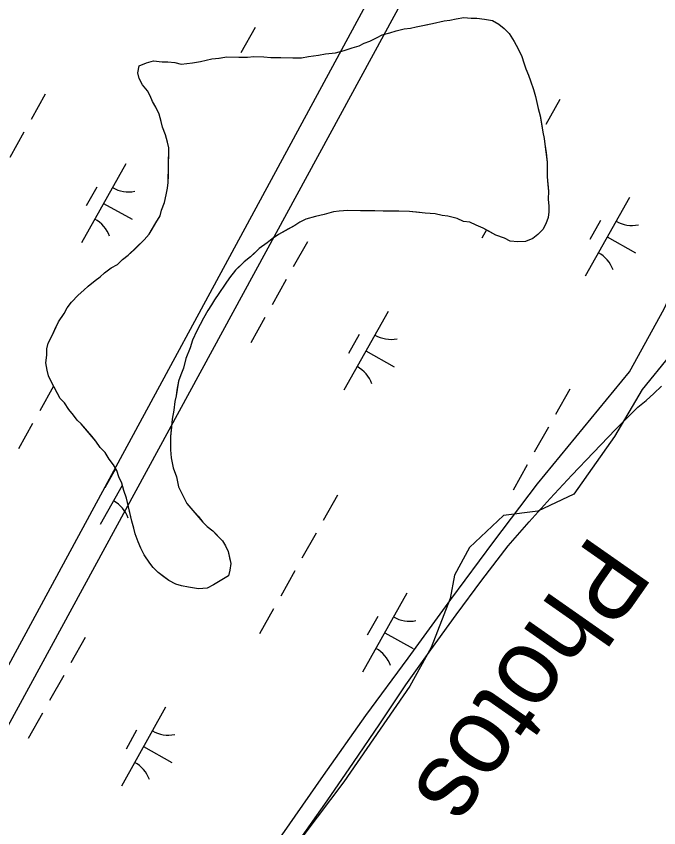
# Model space of a CAD drawing. Extents: x 3913936 to 3933962, y 195330 to 217741.
# Drawn here: x 3926148.2 to 3926503.4, y 209335.7 to 209784.3 of the extents above; entities that cross this region are included whole.
import ezdxf

# ---------------------------------------------------------------- set-up
doc = ezdxf.new("R2010")
doc.units = 0
for name, color, linetype in [('V-RIVR-EDGE', 7, 'Continuous'), ('V-RIVR-IDEN', 7, 'Continuous'), ('V-RRAP-FSHR', 7, 'Continuous'), ('V-TOPO-SHOR', 7, 'Continuous'), ('V-UTIL-LINE', 7, 'Continuous'), ('V-WETL-SWMP', 7, 'Continuous')]:
    doc.layers.add(name, color=color, linetype=linetype)

msp = doc.modelspace()

# ---------------------------------------------------------------- linework, layer by layer
at = {"layer": 'V-RIVR-EDGE'}
msp.add_lwpolyline([(3926892.67, 210182.59), (3926854.95, 210131.91), (3926814.88, 210070.61), (3926787.77, 210030.54), (3926744.16, 209975.14), (3926680.51, 209878.48), (3926634.54, 209811.3), (3926563.81, 209712.28), (3926562.63, 209685.17), (3926537.88, 209634.49), (3926509.59, 209596.77), (3926494.27, 209577.91), (3926478.94, 209551.98), (3926456.55, 209520.15), (3926436.51, 209510.72), (3926417.65, 209508.37), (3926398.79, 209490.69), (3926390.54, 209475.36), (3926388.18, 209462.4), (3926377.58, 209435.29), (3926365.79, 209414.07), (3926329.25, 209361.03), (3926299.78, 209322.13)], dxfattribs=at)
at = {"layer": 'V-RRAP-FSHR'}
msp.add_lwpolyline([(3926144.53, 209096.38), (3926165.14, 209130.13), (3926186.84, 209163.74), (3926208.53, 209197.34), (3926230.22, 209230.95), (3926251.92, 209264.55), (3926273.61, 209298.16), (3926295.31, 209331.77), (3926318.1, 209364.69), (3926341.47, 209397.75), (3926364.94, 209429.46), (3926388.41, 209461.85), (3926412.27, 209493.96), (3926436.47, 209525.8), (3926461.82, 209556.74), (3926487.16, 209587.69), (3926506.32, 209622.52), (3926523.2, 209658.79), (3926542.21, 209693.94), (3926562.2, 209728.58), (3926583.45, 209762.45)], dxfattribs=at)
at = {"layer": 'V-TOPO-SHOR'}
for points in [[(3926250.08, 209759.22), (3926253.23, 209759.97), (3926256.38, 209760.71), (3926260.32, 209761.05), (3926264.65, 209761.78), (3926271.32, 209761.69), (3926276.03, 209761.63), (3926279.57, 209761.98), (3926285.07, 209761.9), (3926288.99, 209761.46), (3926294.49, 209761.38), (3926301.17, 209761.3), (3926305.88, 209761.23), (3926309.82, 209761.97), (3926315.33, 209762.68), (3926319.26, 209763.41), (3926324.77, 209764.12), (3926329.5, 209765.24), (3926333.84, 209766.76), (3926337.78, 209767.88), (3926340.55, 209769.42), (3926343.71, 209770.55), (3926347.66, 209772.46), (3926350.43, 209774), (3926354.77, 209775.12), (3926358.32, 209776.25), (3926362.65, 209777.37), (3926366.19, 209777.72), (3926369.35, 209778.46), (3926374.86, 209779.57), (3926378.4, 209780.31), (3926384.71, 209781.79), (3926387.85, 209782.15), (3926391.4, 209782.88), (3926395.73, 209783.61), (3926399.65, 209783.17), (3926402.79, 209783.12), (3926407.11, 209782.68), (3926411.42, 209781.83), (3926414.93, 209779.82), (3926418.04, 209777.43), (3926420.75, 209774.64), (3926423.44, 209770.28), (3926425.75, 209766.33), (3926427.65, 209761.98), (3926428.78, 209758.43), (3926429.92, 209755.27), (3926431.44, 209751.72), (3926432.58, 209748.56), (3926434.09, 209743.83), (3926435.21, 209739.88), (3926436.7, 209733.19), (3926437.82, 209729.24), (3926438.55, 209724.91), (3926439.27, 209720.19), (3926440.01, 209716.65), (3926440.37, 209713.5), (3926441.09, 209708.78), (3926441.81, 209703.66), (3926441.76, 209700.12), (3926441.7, 209695.42), (3926442.03, 209691.09), (3926442.38, 209687.55), (3926442.32, 209683.23), (3926442.66, 209679.3), (3926442.62, 209676.16), (3926442.19, 209673.02), (3926440.96, 209669.5), (3926439.35, 209666.38), (3926436.56, 209663.67), (3926433.78, 209661.35), (3926429.83, 209659.83), (3926425.51, 209659.49), (3926421.19, 209659.94), (3926418.07, 209661.55), (3926413.38, 209663.19), (3926409.1, 209665.6), (3926406.37, 209667.21), (3926402.46, 209668.83), (3926398.95, 209670.45), (3926395.42, 209670.89), (3926391.9, 209672.51), (3926386.81, 209673.75), (3926383.68, 209674.18), (3926379.76, 209675.02), (3926374.27, 209675.49), (3926369.56, 209675.94), (3926365.64, 209676.39), (3926359.75, 209676.47), (3926355.04, 209676.53), (3926351.11, 209676.58), (3926346.4, 209676.64), (3926341.68, 209676.7), (3926338.54, 209676.75), (3926331.47, 209676.84), (3926326.75, 209676.51), (3926323.61, 209676.16), (3926318.48, 209674.65), (3926313.75, 209673.54), (3926308.23, 209672.04), (3926305.07, 209670.51)], [(3926257.25, 209470.04), (3926253.69, 209468.13), (3926248.97, 209467.79), (3926243.48, 209468.65), (3926239.57, 209469.49), (3926236.44, 209470.32), (3926232.54, 209472.33), (3926229.81, 209474.33), (3926226.7, 209476.73), (3926223.99, 209479.52), (3926222.06, 209481.9), (3926218.98, 209486.65), (3926217.06, 209490.21), (3926215.54, 209493.77), (3926214.02, 209498.11), (3926213.28, 209501.26), (3926212.15, 209505.2), (3926211.41, 209508.36), (3926210.29, 209513.08), (3926209.18, 209517.81), (3926207.66, 209522.15), (3926206.54, 209526.1), (3926205.01, 209529.65), (3926203.88, 209533.2), (3926201.96, 209536.37), (3926199.65, 209539.54), (3926197.34, 209543.11), (3926194.62, 209545.89), (3926192.31, 209549.46), (3926189.99, 209552.24), (3926186.51, 209556.21), (3926184.19, 209558.99), (3926181.86, 209560.99), (3926179.93, 209563.76), (3926177.23, 209566.94), (3926174.92, 209570.5), (3926172.59, 209572.89), (3926171.06, 209575.66), (3926169.14, 209579.22), (3926167.61, 209582.38), (3926166.08, 209585.55), (3926165.34, 209588.7), (3926164.6, 209592.64), (3926165.06, 209596.95), (3926165.1, 209600.48), (3926165.93, 209603.62), (3926167.95, 209607.52), (3926169.56, 209611.03), (3926171.58, 209615.33), (3926174.79, 209619.99), (3926176.4, 209623.12), (3926178.8, 209626.23), (3926182.38, 209630.11), (3926185.56, 209632.82), (3926187.95, 209635.14), (3926191.92, 209638.23), (3926194.69, 209640.16), (3926197.08, 209642.48), (3926200.65, 209645.19), (3926204.21, 209647.1), (3926207, 209649.81), (3926210.17, 209652.13), (3926213.35, 209655.23), (3926215.74, 209657.55), (3926218.92, 209660.65), (3926221.71, 209663.76), (3926223.32, 209666.49), (3926225.33, 209669.99), (3926227.74, 209673.89), (3926228.57, 209677.02), (3926230.19, 209681.32), (3926231.04, 209685.63), (3926231.87, 209689.16), (3926232.3, 209692.29), (3926232.35, 209696.22), (3926232.4, 209699.76), (3926232.45, 209703.29), (3926232.5, 209707.22), (3926232.56, 209711.54), (3926231.81, 209714.69), (3926230.69, 209718.63), (3926229.17, 209722.97), (3926228.43, 209726.12), (3926227.3, 209730.07), (3926225.39, 209734.02), (3926223.47, 209737.19), (3926222.33, 209740.34), (3926220.8, 209743.11), (3926218.09, 209746.29), (3926216.18, 209749.85), (3926215.43, 209753.01), (3926216.27, 209756.92), (3926220.22, 209758.44), (3926224.16, 209759.56), (3926228.87, 209759.11), (3926232.01, 209759.07), (3926235.93, 209758.62), (3926239.46, 209757.79), (3926242.6, 209758.14), (3926245.75, 209758.49), (3926250.08, 209759.22)], [(3926305.07, 209670.51), (3926302.3, 209668.58), (3926298.74, 209666.67), (3926293.2, 209663.6), (3926289.63, 209661.29), (3926286.85, 209658.97), (3926282.49, 209655.88), (3926280.1, 209653.56), (3926277.72, 209651.24), (3926274.15, 209648.53), (3926271.76, 209646.21), (3926269.37, 209643.88), (3926266.17, 209639.61), (3926263.77, 209636.1), (3926260.17, 209631.04), (3926257.76, 209627.54), (3926256.16, 209624.81), (3926254.15, 209621.7), (3926251.74, 209617.41), (3926248.11, 209610.38), (3926245.69, 209605.31), (3926244.45, 209601.01), (3926242.02, 209595.15), (3926240.77, 209589.66), (3926239.15, 209586.15), (3926237.92, 209582.63), (3926237.07, 209577.54), (3926236.64, 209574.4), (3926235.81, 209571.27), (3926235.35, 209566.56), (3926234.5, 209561.47), (3926234.05, 209557.15), (3926233.59, 209552.05), (3926233.54, 209548.13), (3926233.49, 209544.59), (3926233.83, 209540.27), (3926234.93, 209534.75), (3926236.83, 209529.62), (3926237.93, 209524.11), (3926240.61, 209518.57), (3926242.53, 209515.01), (3926245.62, 209511.44), (3926248.72, 209507.86), (3926251.42, 209504.68), (3926253.75, 209502.3), (3926256.86, 209499.9), (3926259.19, 209497.51), (3926262.29, 209494.33), (3926263.82, 209491.56), (3926265.35, 209488.4), (3926266.09, 209484.85), (3926266.83, 209481.7), (3926266.39, 209478.17), (3926265.56, 209475.04), (3926257.25, 209470.04)]]:
    msp.add_lwpolyline(points, dxfattribs=at)
at = {"layer": 'V-UTIL-LINE'}
for points in [[(3928315.82, 212388.13), (3926944.7, 210748.94), (3926592.74, 210251.47), (3926408.93, 209914.99), (3925628.64, 208474.44), (3925139.98, 207727.42), (3924555.96, 206253.65), (3924055.82, 204771.45), (3923484.9, 203858.52), (3922256.01, 202262.65), (3921816.4, 201905.57), (3920704.84, 200345.08), (3920462.44, 200062.72)], [(3928328.32, 212380.93), (3926784.14, 210502.92), (3926424.72, 209908.68), (3925640.45, 208467.64), (3924952.2, 207329.25), (3923971.74, 204752.16), (3923252.9, 203563.68), (3921560.17, 201558.84), (3920397.87, 200112.86)]]:
    msp.add_lwpolyline(points, dxfattribs=at)
at = {"layer": 'V-WETL-SWMP'}
for p, q in [((3926378.4, 209780.31), (3926384.71, 209781.79)), ((3926384.71, 209781.79), (3926387.85, 209782.15)), ((3926387.85, 209782.15), (3926391.4, 209782.88)), ((3926391.4, 209782.88), (3926395.73, 209783.61)), ((3926395.73, 209783.61), (3926399.65, 209783.17)), ((3926399.65, 209783.17), (3926402.79, 209783.12)), ((3926402.79, 209783.12), (3926407.11, 209782.68)), ((3926407.11, 209782.68), (3926411.42, 209781.83)), ((3926411.42, 209781.83), (3926414.93, 209779.82)), ((3926280.24, 209777.95), (3926272.4, 209764.01)), ((3926358.32, 209776.25), (3926362.65, 209777.37)), ((3926362.65, 209777.37), (3926366.19, 209777.72)), ((3926366.19, 209777.72), (3926369.35, 209778.46)), ((3926369.35, 209778.46), (3926378.4, 209780.31)), ((3926414.93, 209779.82), (3926418.04, 209777.43)), ((3926418.04, 209777.43), (3926420.75, 209774.64)), ((3926343.71, 209770.55), (3926347.66, 209772.46)), ((3926347.66, 209772.46), (3926350.43, 209774)), ((3926350.43, 209774), (3926354.77, 209775.12)), ((3926354.77, 209775.12), (3926358.32, 209776.25)), ((3926420.75, 209774.64), (3926423.44, 209770.28)), ((3926337.78, 209767.88), (3926340.55, 209769.42)), ((3926340.55, 209769.42), (3926343.71, 209770.55)), ((3926423.44, 209770.28), (3926425.75, 209766.33)), ((3926315.33, 209762.68), (3926319.26, 209763.41)), ((3926319.26, 209763.41), (3926324.77, 209764.13)), ((3926324.77, 209764.13), (3926329.5, 209765.24)), ((3926329.5, 209765.24), (3926333.84, 209766.76)), ((3926333.84, 209766.76), (3926337.78, 209767.88)), ((3926425.75, 209766.33), (3926427.65, 209761.98)), ((3926220.22, 209758.44), (3926224.16, 209759.57)), ((3926224.16, 209759.57), (3926228.87, 209759.11)), ((3926228.87, 209759.11), (3926232.01, 209759.07)), ((3926232.01, 209759.07), (3926235.93, 209758.62)), ((3926245.75, 209758.49), (3926250.08, 209759.22)), ((3926250.08, 209759.22), (3926256.38, 209760.71)), ((3926256.38, 209760.71), (3926260.31, 209761.05)), ((3926260.31, 209761.05), (3926264.65, 209761.78)), ((3926264.65, 209761.78), (3926276.03, 209761.63)), ((3926276.03, 209761.63), (3926279.57, 209761.97)), ((3926279.57, 209761.97), (3926285.07, 209761.9)), ((3926285.07, 209761.9), (3926288.99, 209761.46)), ((3926288.99, 209761.46), (3926305.88, 209761.23)), ((3926305.88, 209761.23), (3926309.82, 209761.97)), ((3926309.82, 209761.97), (3926315.33, 209762.68)), ((3926427.65, 209761.98), (3926428.78, 209758.43)), ((3926215.43, 209753), (3926216.27, 209756.92)), ((3926216.27, 209756.92), (3926220.22, 209758.44)), ((3926235.93, 209758.62), (3926239.46, 209757.79)), ((3926239.46, 209757.79), (3926245.75, 209758.49)), ((3926428.78, 209758.43), (3926429.92, 209755.27)), ((3926429.92, 209755.27), (3926431.44, 209751.72)), ((3926216.18, 209749.85), (3926215.43, 209753)), ((3926431.44, 209751.72), (3926432.58, 209748.56)), ((3926218.09, 209746.29), (3926216.18, 209749.85)), ((3926220.8, 209743.11), (3926218.09, 209746.29)), ((3926432.58, 209748.56), (3926434.09, 209743.83)), ((3926164.23, 209741.13), (3926156.39, 209727.18)), ((3926222.33, 209740.34), (3926220.8, 209743.11)), ((3926434.09, 209743.83), (3926435.21, 209739.88)), ((3926223.47, 209737.19), (3926222.33, 209740.34)), ((3926225.39, 209734.02), (3926223.47, 209737.19)), ((3926435.21, 209739.88), (3926436.7, 209733.19)), ((3926448.76, 209738.29), (3926440.92, 209724.34)), ((3926227.3, 209730.07), (3926225.39, 209734.02)), ((3926436.7, 209733.19), (3926437.82, 209729.24)), ((3926228.43, 209726.12), (3926227.3, 209730.07)), ((3926437.82, 209729.24), (3926439.27, 209720.19)), ((3926229.17, 209722.97), (3926228.43, 209726.12)), ((3926152.47, 209720.21), (3926144.63, 209706.26)), ((3926230.69, 209718.63), (3926229.17, 209722.97)), ((3926231.81, 209714.69), (3926230.69, 209718.63)), ((3926439.27, 209720.19), (3926440.01, 209716.65)), ((3926232.56, 209711.54), (3926231.81, 209714.69)), ((3926440.01, 209716.65), (3926440.37, 209713.5)), ((3926232.3, 209692.29), (3926232.56, 209711.54)), ((3926440.37, 209713.5), (3926441.81, 209703.66)), ((3926208.8, 209702.64), (3926184.3, 209659.06)), ((3926441.81, 209703.66), (3926441.7, 209695.41)), ((3926231.87, 209689.16), (3926232.3, 209692.29)), ((3926441.7, 209695.41), (3926442.38, 209687.55)), ((3926192.77, 209689.86), (3926186.89, 209679.4)), ((3926231.04, 209685.63), (3926231.87, 209689.16)), ((3926442.38, 209687.55), (3926442.32, 209683.23)), ((3926230.19, 209681.32), (3926231.04, 209685.63)), ((3926442.32, 209683.23), (3926442.66, 209679.3)), ((3926487.17, 209684.09), (3926462.67, 209640.51)), ((3926196.55, 209680.85), (3926212.24, 209672.03)), ((3926228.57, 209677.02), (3926230.19, 209681.32)), ((3926442.66, 209679.3), (3926442.62, 209676.15)), ((3926225.33, 209670), (3926227.74, 209673.89)), ((3926227.74, 209673.89), (3926228.57, 209677.02)), ((3926318.48, 209674.65), (3926313.75, 209673.54)), ((3926323.61, 209676.16), (3926318.48, 209674.65)), ((3926326.75, 209676.51), (3926323.61, 209676.16)), ((3926331.47, 209676.84), (3926326.75, 209676.51)), ((3926365.64, 209676.39), (3926331.47, 209676.84)), ((3926374.27, 209675.49), (3926365.64, 209676.39)), ((3926379.76, 209675.02), (3926374.27, 209675.49)), ((3926383.68, 209674.19), (3926379.76, 209675.02)), ((3926386.81, 209673.75), (3926383.68, 209674.19)), ((3926391.9, 209672.51), (3926386.81, 209673.75)), ((3926442.62, 209676.15), (3926442.19, 209673.02)), ((3926221.71, 209663.76), (3926225.33, 209670)), ((3926305.07, 209670.51), (3926302.3, 209668.59)), ((3926308.23, 209672.04), (3926305.07, 209670.51)), ((3926313.75, 209673.54), (3926308.23, 209672.04)), ((3926395.42, 209670.89), (3926391.9, 209672.51)), ((3926398.95, 209670.45), (3926395.42, 209670.89)), ((3926402.46, 209668.83), (3926398.95, 209670.45)), ((3926440.96, 209669.5), (3926439.35, 209666.38)), ((3926442.19, 209673.02), (3926440.96, 209669.5)), ((3926471.13, 209671.31), (3926465.25, 209660.85)), ((3926302.3, 209668.59), (3926293.2, 209663.6)), ((3926406.37, 209667.21), (3926402.46, 209668.83)), ((3926408.21, 209666.15), (3926405.64, 209661.58)), ((3926413.38, 209663.19), (3926406.37, 209667.21)), ((3926439.35, 209666.38), (3926436.56, 209663.67)), ((3926210.17, 209652.13), (3926218.92, 209660.65)), ((3926218.92, 209660.65), (3926221.71, 209663.76)), ((3926289.63, 209661.29), (3926286.85, 209658.97)), ((3926293.2, 209663.6), (3926289.63, 209661.29)), ((3926418.07, 209661.55), (3926413.38, 209663.19)), ((3926421.2, 209659.94), (3926418.07, 209661.55)), ((3926433.78, 209661.35), (3926429.83, 209659.83)), ((3926436.56, 209663.67), (3926433.78, 209661.35)), ((3926474.92, 209662.3), (3926490.61, 209653.48)), ((3926282.49, 209655.89), (3926277.72, 209651.24)), ((3926286.85, 209658.97), (3926282.49, 209655.89)), ((3926309.22, 209659.62), (3926301.38, 209645.67)), ((3926425.51, 209659.49), (3926421.2, 209659.94)), ((3926429.83, 209659.83), (3926425.51, 209659.49)), ((3926207, 209649.81), (3926210.17, 209652.13)), ((3926200.65, 209645.18), (3926204.21, 209647.1)), ((3926204.21, 209647.1), (3926207, 209649.81)), ((3926274.15, 209648.53), (3926269.37, 209643.88)), ((3926277.72, 209651.24), (3926274.15, 209648.53)), ((3926194.69, 209640.16), (3926197.08, 209642.48)), ((3926197.08, 209642.48), (3926200.65, 209645.18)), ((3926269.37, 209643.88), (3926266.17, 209639.6)), ((3926187.95, 209635.14), (3926191.92, 209638.23)), ((3926191.92, 209638.23), (3926194.69, 209640.16)), ((3926266.17, 209639.6), (3926257.76, 209627.54)), ((3926297.46, 209638.7), (3926289.62, 209624.75)), ((3926185.56, 209632.82), (3926187.95, 209635.14)), ((3926178.8, 209626.23), (3926182.38, 209630.11)), ((3926182.38, 209630.11), (3926185.56, 209632.82)), ((3926176.4, 209623.12), (3926178.8, 209626.23)), ((3926256.16, 209624.81), (3926254.15, 209621.7)), ((3926257.76, 209627.54), (3926256.16, 209624.81)), ((3926171.58, 209615.33), (3926174.79, 209620)), ((3926174.79, 209620), (3926176.4, 209623.12)), ((3926254.15, 209621.7), (3926251.74, 209617.41)), ((3926353.8, 209621.13), (3926329.3, 209577.55)), ((3926251.74, 209617.41), (3926248.11, 209610.39)), ((3926285.7, 209617.78), (3926277.86, 209603.83)), ((3926167.94, 209607.52), (3926171.58, 209615.33)), ((3926165.93, 209603.62), (3926167.94, 209607.52)), ((3926248.11, 209610.39), (3926245.69, 209605.31)), ((3926337.77, 209608.35), (3926331.88, 209597.89)), ((3926165.1, 209600.49), (3926165.93, 209603.62)), ((3926245.69, 209605.31), (3926244.45, 209601.01)), ((3926165.06, 209596.95), (3926165.1, 209600.49)), ((3926244.45, 209601.01), (3926242.02, 209595.15)), ((3926341.55, 209599.34), (3926357.24, 209590.52)), ((3926164.6, 209592.64), (3926165.06, 209596.95)), ((3926242.02, 209595.15), (3926240.77, 209589.67)), ((3926165.34, 209588.7), (3926164.6, 209592.64)), ((3926166.08, 209585.55), (3926165.34, 209588.7)), ((3926240.77, 209589.67), (3926239.15, 209586.15)), ((3926169.14, 209579.22), (3926166.08, 209585.55)), ((3926239.15, 209586.15), (3926237.92, 209582.63)), ((3926168.86, 209579.81), (3926161.19, 209566.17)), ((3926237.92, 209582.63), (3926236.64, 209574.4)), ((3926500.77, 209575.75), (3926504.97, 209579.79)), ((3926172.59, 209572.89), (3926169.14, 209579.22)), ((3926454.22, 209578.11), (3926446.38, 209564.16)), ((3926496.43, 209571.88), (3926500.77, 209575.75)), ((3926174.92, 209570.5), (3926172.59, 209572.89)), ((3926235.81, 209571.27), (3926235.35, 209566.56)), ((3926236.64, 209574.4), (3926235.81, 209571.27)), ((3926491.94, 209568.16), (3926496.43, 209571.88)), ((3926177.23, 209566.94), (3926174.92, 209570.5)), ((3926179.93, 209563.76), (3926177.23, 209566.94)), ((3926235.35, 209566.56), (3926234.5, 209561.47)), ((3926479.59, 209555.76), (3926491.94, 209568.16)), ((3926181.86, 209560.99), (3926179.93, 209563.76)), ((3926157.27, 209559.2), (3926149.43, 209545.25)), ((3926184.19, 209558.99), (3926181.86, 209560.99)), ((3926192.31, 209549.46), (3926184.19, 209558.99)), ((3926234.5, 209561.47), (3926233.59, 209552.05)), ((3926442.46, 209557.19), (3926434.62, 209543.24)), ((3926467.39, 209543.21), (3926479.59, 209555.76)), ((3926194.62, 209545.89), (3926192.31, 209549.46)), ((3926233.59, 209552.05), (3926233.49, 209544.59)), ((3926197.34, 209543.11), (3926194.62, 209545.89)), ((3926233.49, 209544.59), (3926233.83, 209540.27)), ((3926199.65, 209539.54), (3926197.34, 209543.11)), ((3926201.96, 209536.37), (3926199.65, 209539.54)), ((3926233.83, 209540.27), (3926234.93, 209534.75)), ((3926455.34, 209530.53), (3926467.39, 209543.21)), ((3926203.88, 209533.2), (3926201.96, 209536.37)), ((3926234.93, 209534.75), (3926236.83, 209529.62)), ((3926430.7, 209536.27), (3926422.86, 209522.32)), ((3926203.16, 209534.06), (3926197.28, 209523.6)), ((3926205.01, 209529.65), (3926203.88, 209533.2)), ((3926443.44, 209517.69), (3926455.34, 209530.53)), ((3926206.54, 209526.1), (3926205.01, 209529.65)), ((3926207.66, 209522.15), (3926206.54, 209526.1)), ((3926236.83, 209529.62), (3926237.93, 209524.11)), ((3926206.87, 209524.92), (3926194.7, 209503.26)), ((3926209.18, 209517.81), (3926207.66, 209522.15)), ((3926237.93, 209524.11), (3926240.61, 209518.57)), ((3926212.15, 209505.2), (3926209.18, 209517.81)), ((3926240.61, 209518.57), (3926242.53, 209515.01)), ((3926325.79, 209519.53), (3926317.95, 209505.58)), ((3926431.69, 209504.72), (3926443.44, 209517.69)), ((3926242.53, 209515.01), (3926251.42, 209504.68)), ((3926213.28, 209501.26), (3926212.15, 209505.2)), ((3926251.42, 209504.68), (3926253.75, 209502.3)), ((3926420.1, 209491.61), (3926431.69, 209504.72)), ((3926214.02, 209498.11), (3926213.28, 209501.26)), ((3926253.75, 209502.3), (3926256.86, 209499.9)), ((3926256.86, 209499.9), (3926262.29, 209494.33)), ((3926215.54, 209493.77), (3926214.02, 209498.11)), ((3926262.29, 209494.33), (3926263.82, 209491.56)), ((3926314.03, 209498.61), (3926306.19, 209484.66)), ((3926217.06, 209490.21), (3926215.54, 209493.77)), ((3926218.98, 209486.65), (3926217.06, 209490.21)), ((3926263.82, 209491.56), (3926265.35, 209488.4)), ((3926405.64, 209472.62), (3926420.1, 209491.61)), ((3926222.06, 209481.9), (3926218.98, 209486.65)), ((3926265.35, 209488.4), (3926266.83, 209481.7)), ((3926223.99, 209479.52), (3926222.06, 209481.9)), ((3926266.83, 209481.7), (3926266.39, 209478.17)), ((3926226.7, 209476.73), (3926223.99, 209479.52)), ((3926232.54, 209472.33), (3926226.7, 209476.73)), ((3926266.39, 209478.17), (3926265.56, 209475.04)), ((3926302.27, 209477.69), (3926294.43, 209463.74)), ((3926236.44, 209470.32), (3926232.54, 209472.33)), ((3926265.56, 209475.04), (3926257.25, 209470.04)), ((3926391.39, 209453.46), (3926405.64, 209472.62)), ((3926239.57, 209469.49), (3926236.44, 209470.32)), ((3926243.48, 209468.65), (3926239.57, 209469.49)), ((3926248.97, 209467.79), (3926243.48, 209468.65)), ((3926253.69, 209468.12), (3926248.97, 209467.79)), ((3926257.25, 209470.04), (3926253.69, 209468.12)), ((3926364.2, 209465.33), (3926339.69, 209421.75)), ((3926290.51, 209456.77), (3926282.67, 209442.82)), ((3926348.16, 209452.55), (3926342.28, 209442.09)), ((3926377.37, 209434.14), (3926391.39, 209453.46)), ((3926186.25, 209440.86), (3926178.41, 209426.91)), ((3926351.95, 209443.54), (3926367.64, 209434.72)), ((3926363.56, 209414.67), (3926377.37, 209434.14)), ((3926174.49, 209419.94), (3926166.65, 209405.99)), ((3926349.24, 209393.18), (3926363.56, 209414.67)), ((3926230.83, 209402.37), (3926206.33, 209358.79)), ((3926162.73, 209399.02), (3926154.89, 209385.07)), ((3926334.74, 209371.83), (3926349.24, 209393.18)), ((3926214.79, 209389.59), (3926208.91, 209379.13)), ((3926218.58, 209380.58), (3926234.27, 209371.76)), ((3926320.06, 209350.59), (3926334.74, 209371.83)), ((3926305.19, 209329.49), (3926320.06, 209350.59))]:
    msp.add_line(p, q, dxfattribs=at)
for centre, start, end in [((3926210.29, 209704.81), 239.8861, 281.4297), ((3926183.22, 209656.66), 19.8861, 61.4297), ((3926488.66, 209686.26), 239.8861, 281.4297), ((3926461.59, 209638.11), 19.8861, 61.4297), ((3926355.29, 209623.3), 239.8861, 281.4297), ((3926328.22, 209575.15), 19.8861, 61.4297), ((3926193.62, 209500.86), 19.8861, 61.4297), ((3926365.69, 209467.5), 239.8861, 281.4297), ((3926338.62, 209419.35), 19.8861, 61.4297), ((3926232.32, 209404.54), 239.8861, 281.4297), ((3926205.25, 209356.39), 19.8861, 61.4297)]:
    msp.add_arc(centre, 17.62, start, end, dxfattribs=at)

# ---------------------------------------------------------------- texts
at = {"layer": 'V-RIVR-IDEN'}
msp.add_text('Photos', height=42, rotation=235.0096, dxfattribs=at).set_placement((3926466.35, 209499.1))

doc.saveas('drawing.dxf')
